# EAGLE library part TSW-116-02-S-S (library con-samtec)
THROUGH-HOLE .025" SQ POST HEADER Source: Samtec TSW.pdf
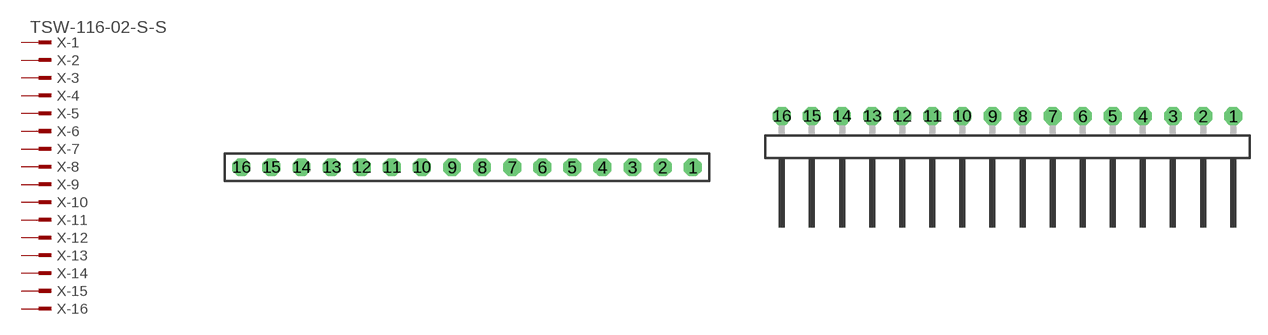
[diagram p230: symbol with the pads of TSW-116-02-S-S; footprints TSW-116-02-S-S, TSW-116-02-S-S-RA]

Designator prefix X; gates -1=MPINV -2=MPIN -3=MPIN -4=MPIN -5=MPIN -6=MPIN -7=MPIN -8=MPIN -9=MPIN -10=MPIN -11=MPIN -12=MPIN -13=MPIN -14=MPIN -15=MPIN -16=MPIN

## TSW-116-02-S-S (OC_FARNELL: unknown; OC_NEWARK: unknown)  [TSW-116-02-S-S]
1  -1:1  pas
2  -2:1  pas
3  -3:1  pas
4  -4:1  pas
5  -5:1  pas
6  -6:1  pas
7  -7:1  pas
8  -8:1  pas
9  -9:1  pas
10  -10:1  pas
11  -11:1  pas
12  -12:1  pas
13  -13:1  pas
14  -14:1  pas
15  -15:1  pas
16  -16:1  pas

## TSW-116-02-S-S-RA (OC_FARNELL: unknown; OC_NEWARK: unknown)  [TSW-116-02-S-S-RA]
Pads as for TSW-116-02-S-S

## Footprint TSW-116-02-S-S (pad centres in mm)
THROUGH-HOLE .025" SQ POST HEADER Source: Samtec TSW.pdf
drill 1 pad 1.5 octagon: 1 19.05,0; 2 16.51,0; 3 13.97,0; 4 11.43,0; 5 8.89,0; 6 6.35,0; 7 3.81,0; 8 1.27,0; 9 -1.27,0; 10 -3.81,0; 11 -6.35,0; 12 -8.89,0; 13 -11.43,0; 14 -13.97,0; 15 -16.51,0; 16 -19.05,0

## Footprint TSW-116-02-S-S-RA (pad centres in mm)
THROUGH-HOLE .025" SQ POST HEADER Source: Samtec TSW.pdf
drill 1 pad 1.5 octagon: 1 19.05,1.524; 2 16.51,1.524; 3 13.97,1.524; 4 11.43,1.524; 5 8.89,1.524; 6 6.35,1.524; 7 3.81,1.524; 8 1.27,1.524; 9 -1.27,1.524; 10 -3.81,1.524; 11 -6.35,1.524; 12 -8.89,1.524; 13 -11.43,1.524; 14 -13.97,1.524; 15 -16.51,1.524; 16 -19.05,1.524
